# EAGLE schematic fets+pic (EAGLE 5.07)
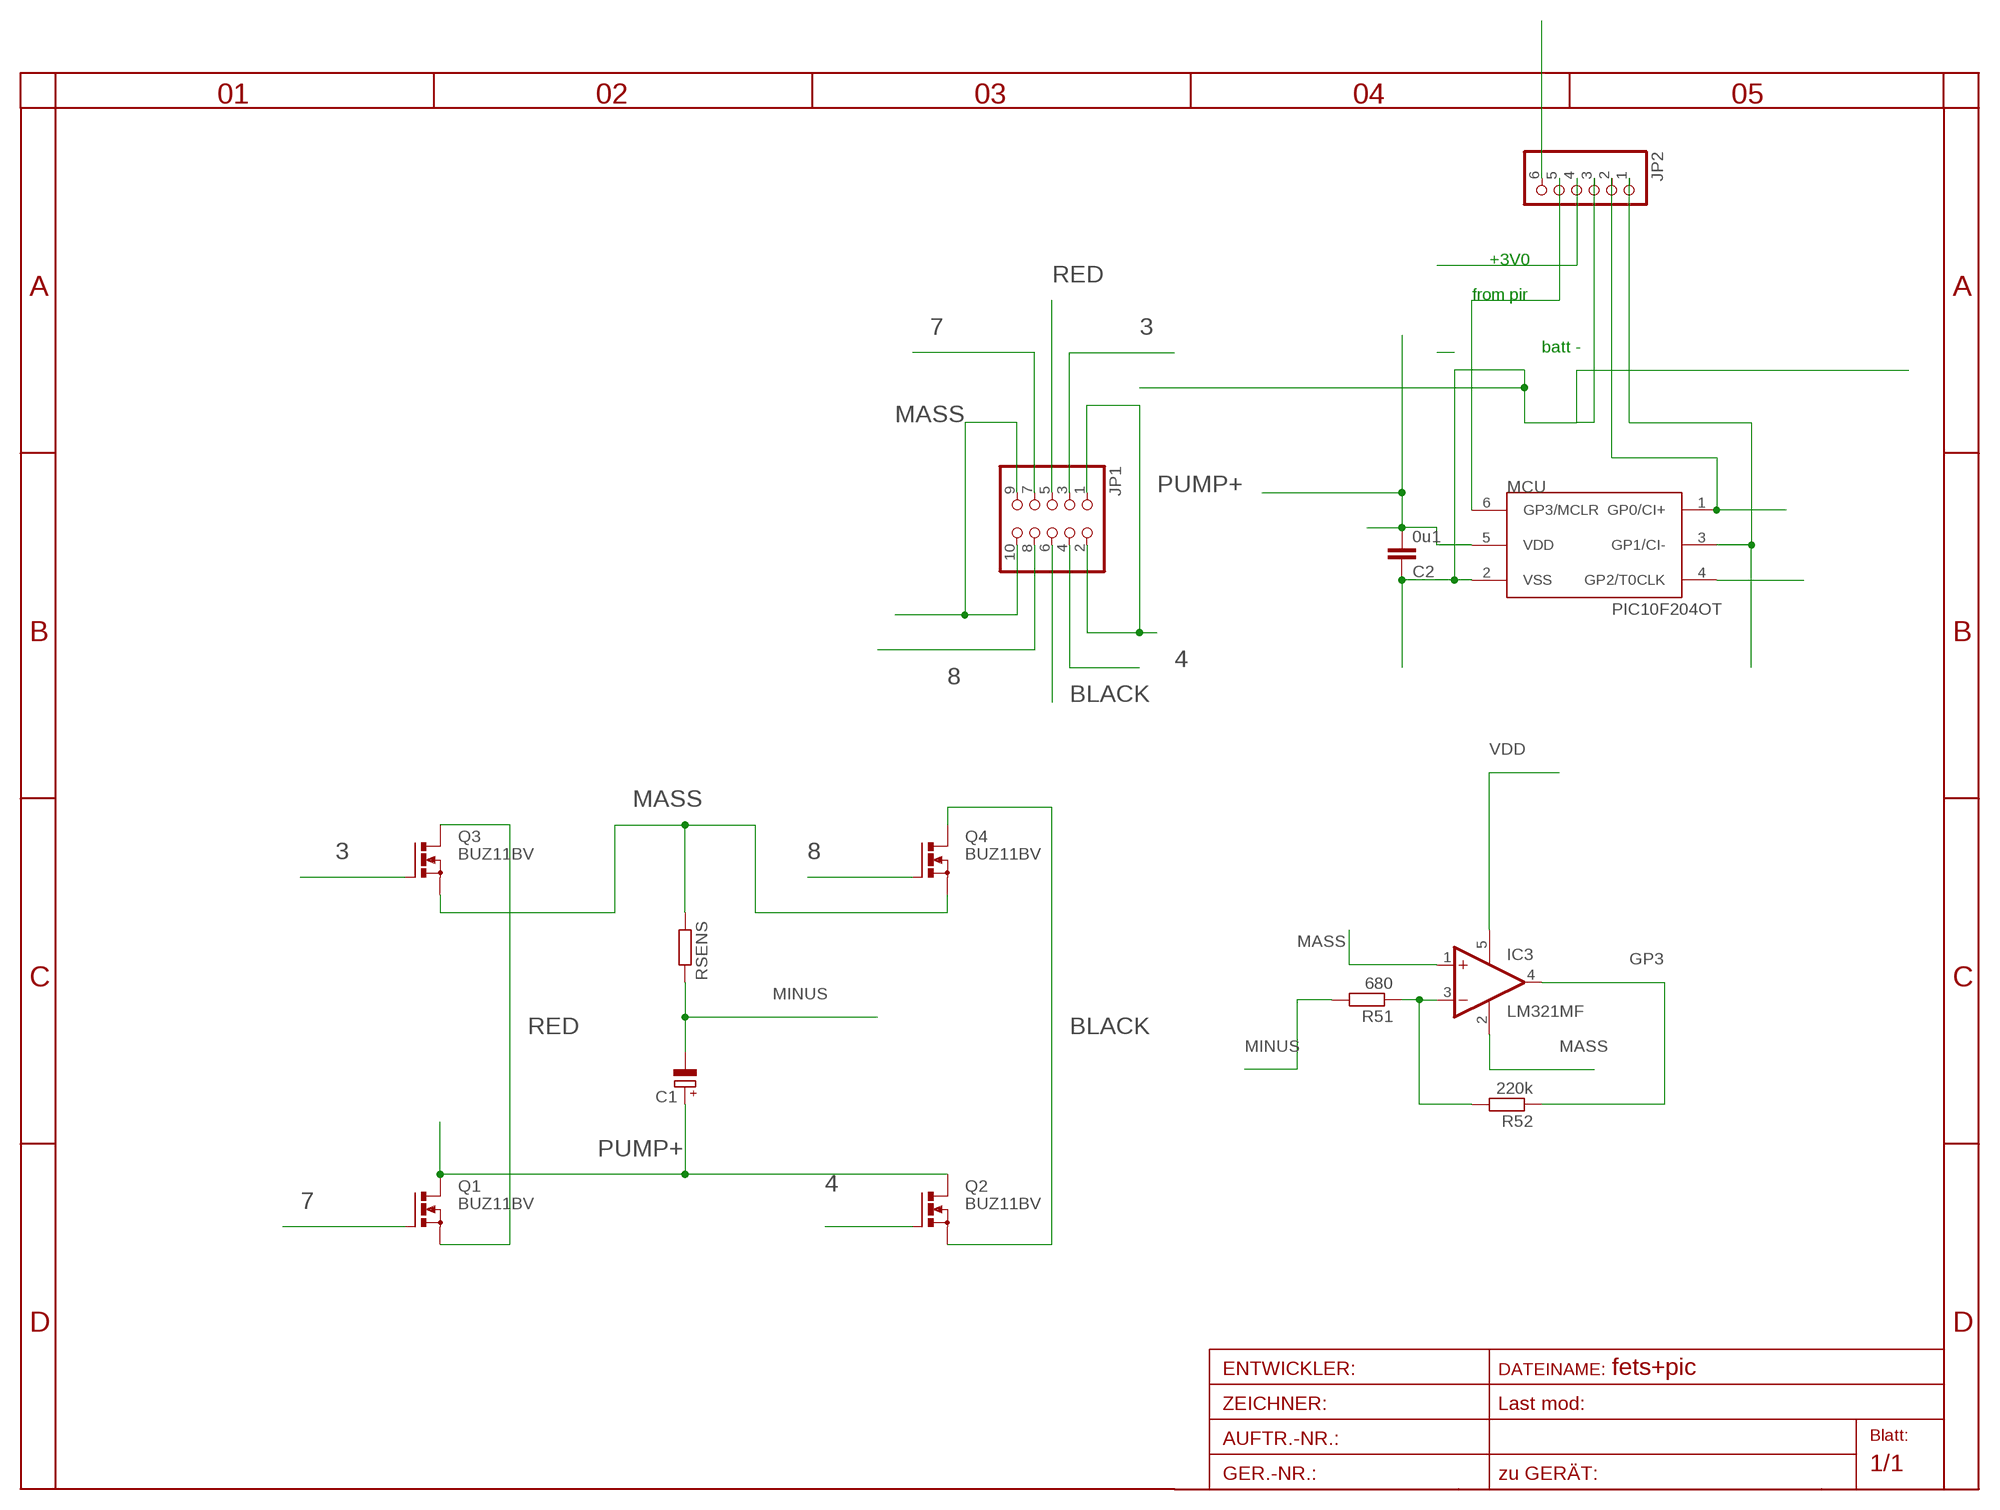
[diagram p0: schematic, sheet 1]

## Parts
C1  CPOL-EUE5-13  [E5-13]
C2  0u1  C-EUC1206  [C1206]
IC3  LM321MF  [SOT23-5]
JP1  PINHD-2X5  [2X05]
JP2  PINHD-1X6  [1X06BOX]
MCU  PIC10F204OT  [SOT23-6]
Q1  BUZ11BV  [TO220BV]
Q2  BUZ11BV  [TO220BV]
Q3  BUZ11BV  [TO220BV]
Q4  BUZ11BV  [TO220BV]
R51  680  R-EU_0207/10  [0207/10]
R52  220k  R-EU_0207/10  [0207/10]
RSENS  R-EU_0207/10  [0207/10]

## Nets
3: JP1.3 Q3.G
4: JP1.4 Q2.G
7: JP1.7 Q1.G
8: JP1.8 Q4.G
BATT+: JP2.6
BLACK: JP1.6 Q2.S Q4.D
GP3: IC3.4(OUT) JP2.5 MCU.6(GP3/MCLR) R52.1
MASS: C2.1 IC3.1(+IN) IC3.2(V-) JP1.9 JP1.10 JP2.3 MCU.2(VSS) Q3.S Q4.S RSENS.1
MINUS: C1.- R51.2 RSENS.2
N$4: JP2.2 MCU.1(GP0/CI+)
N$5: MCU.4(GP2/T0CLK)
N$8: JP2.1 MCU.3(GP1/CI-)
N$52: IC3.3(-IN) R51.1 R52.2
PUMP+: C1.+ JP1.1 JP1.2 Q1.D Q2.D
RED: JP1.5 Q1.S Q3.D
VDD: C2.2 IC3.5(V+) JP2.4 MCU.5(VDD)

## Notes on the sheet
- +3V0
- from pir
- batt -

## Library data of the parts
C1 = rcl:CPOL-EU: POLARIZED CAPACITOR, European symbol
C2 = rcl:C-EU: CAPACITOR, European symbol
IC3 = linear:LM321?*: Low Power Single Op Amp Source: http://cache.national.com/ds/LM/LM321.pdf
JP1 = pinhead:PINHD-2X5: PIN HEADER
JP2 = pinhead:PINHD-1X6: PIN HEADER
MCU = microchip-3:PIC10F2*: uPC nW 0,25/0,5k Program Flash memory Comparator
Q1-Q4 = transistor-power:BUZ11: N-CHANNEL MOS FET
R51 R52 RSENS = rcl:R-EU_: RESISTOR, European symbol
